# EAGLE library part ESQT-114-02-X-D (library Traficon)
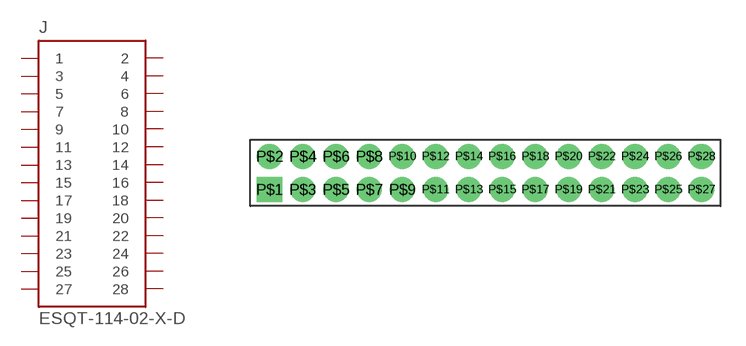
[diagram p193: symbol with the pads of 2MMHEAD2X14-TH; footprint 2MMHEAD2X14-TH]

Designator prefix J

## ESQT-114-02-X-D  [2MMHEAD2X14-TH]
P$1  1  pas
P$2  2  pas
P$3  3  pas
P$4  4  pas
P$5  5  pas
P$6  6  pas
P$7  7  pas
P$8  8  pas
P$9  9  pas
P$10  10  pas
P$11  11  pas
P$12  12  pas
P$13  13  pas
P$14  14  pas
P$15  15  pas
P$16  16  pas
P$17  17
P$18  18
P$19  19
P$20  20
P$21  21
P$22  22
P$23  23
P$24  24
P$25  25
P$26  26
P$27  27
P$28  28

## Footprint 2MMHEAD2X14-TH (pad centres in mm)
drill 1 square: P$1 -13,-1
drill 1 round: P$2 -13,1; P$3 -11,-1; P$4 -11,1; P$5 -9,-1; P$6 -9,1; P$7 -7,-1; P$8 -7,1; P$9 -5,-1; P$10 -5,1; P$11 -3,-1; P$12 -3,1; P$13 -1,-1; P$14 -1,1; P$15 1,-1; P$16 1,1; P$17 3,-1; P$18 3,1; P$19 5,-1; P$20 5,1; P$21 7,-1; P$22 7,1; P$23 9,-1; P$24 9,1; P$25 11,-1; P$26 11,1; P$27 13,-1; P$28 13,1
